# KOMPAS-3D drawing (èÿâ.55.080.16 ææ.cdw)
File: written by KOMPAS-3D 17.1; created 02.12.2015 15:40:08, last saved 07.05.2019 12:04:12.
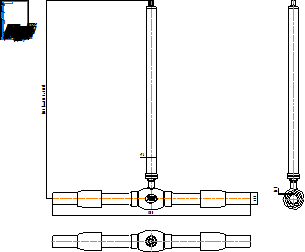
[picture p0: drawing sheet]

Sheet 1: A4, portrait

Title block, sheet 1: name: КШГ.55.080.16 СС; material: Внимание! Данный продукт является объектом авторского права ООО «Торговый Дом АДЛ». / Запрещается изменение, копирование, распространение / (в том числе путем копирования на другие сайты и ресурсы в Интернете) / или любое иное использование информации и объектов без предварительного / согласия правообладателя (ООО «Торговый Дом АДЛ»).; sheets: 1; organisation: ООО "Торговый дом АДЛ"; sheet format: A4; stored path: C:\Users\kka\KOMPAS_Work\Модели кранов для исследований\DN50\С удлинением\КШГ.32.050.40 СС ГЧ _ Шаровой кран БИВАЛ Ду50 Ру4 МПа редуцированный под приварку, с удлинением штока H=1100.cdw; drawn by: Климкович К.А.; drawn by, date: 02.12.15

Views: Вид 1, Проекционный вид 2
Referenced files in C:\Users\kka\KOMPAS_Work\Модели кранов для исследований\DN80\С удлинением\: КШТ.22.080.25 СС.a3d, КШГ.35.065.25 СС.a3d!КШГ.45.065.10 СС!Деталь (локальная).m3d
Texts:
  Klimkovich
  ADL
  (от 380 до 5000)
Dimensions and other numbers on the sheet: 1500; 90; 76; 10,1; 1:1; 1; 02.12.15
